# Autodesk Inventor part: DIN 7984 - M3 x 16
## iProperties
Created: 2004-01
Part Number: DIN 7984 - M3 x 16
Material: Standard
Catalog Web Link: file:///C:/Programme/Autodesk/Inventor 5.3/Content/Din/index.htm?doNavigateId=7A3AD695-C431-11D4-A9F1-0080AD303E0A|31199CD8B16811D4BA6900C04F798F98|true
Description: Zylinderschraube
Document SubType Name: Standard Catalog Part
Standard: DIN 7984 - M3 x 16
Designer: Ulrich
Control State: 0
Master: False
Checked Out: False
Shininess: 20.0
Angle Display Precision: 2
Document Length Units: 11269
Document Angle Units: 11279
Document Time Units: 11290
Document Mass Units: 11283
Document Length Units Precision: 3
Document Angle Units Precision: 2
Compacted: True
KLASSIFIKATION: 31161501 un/spsc
HERSTELLER: DIN Normsystem
Density: 0.0
Volumn: 0.0
Area: 0.0
PropertySet Name: Model Information
Author: Ulrich
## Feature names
1. Basis1
